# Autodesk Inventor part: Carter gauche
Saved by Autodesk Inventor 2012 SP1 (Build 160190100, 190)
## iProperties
Created: 2014-12
Part Number: Carter gauche
Material: Default
Document SubType Name: Modeling
Designer: Bruno
Density: 1 g/cm^3
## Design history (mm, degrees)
node "Carter gauche1"
node "Carter gauche"
node "Base1"
